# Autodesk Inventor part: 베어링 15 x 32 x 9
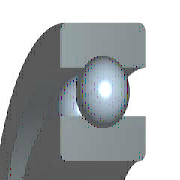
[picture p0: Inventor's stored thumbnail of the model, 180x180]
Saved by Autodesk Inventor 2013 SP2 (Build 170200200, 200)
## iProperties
IsCustomPart: 0
Created: 2012-02
Part Number: 베어링 15 x 32 x 9
Material: 강철, 연강
Description: 깊은 그루브 볼 베어링
Document SubType Name: Modeling
Standard: KS B 2023
Designer: mduedu
Standards Organization: KS
Language: ko-KR
Size Designation: 6002 - 15 x 32 x 9
Categories: <MemberInstance><Categories><Category DisplayName="샤프트 부품" InternalName="7f7aeb1f-a693-4053-b835-cee3144e0d98" Mnemonic="SHFT"><Category DisplayName="베어링" Inter
Density: 1 g/cm^3
Author: mduedu
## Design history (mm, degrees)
sketch "스케치" dims "d0" = 4.42 (= -0.26 x WD + 0.26 x BD)
  geometry: L1 (2.29, 11.75)-(6.71, 11.75); L2 (4.5, 11.75)-(4.5, 9.54); L3 (4.5, 11.75)-(4.5, 13.96); L4 (2.858, 10.271)-(0, 10.271); L5 (0, 7.5)-(9, 7.5); L6 (2.858, 13.229)-(0, 13.229); L7 (0, 16)-(9, 16); L8 (9, 7.5)-(9, 10.271); L9 (6.142, 10.271)-(9, 10.271); L10 (6.142, 13.229)-(9, 13.229); L11 (9, 16)-(9, 13.229); L12 (-1.4, 0)-(8.4, 0) reference; L13 (0, -0.3)-(0, 5.3) reference
  constraints: 22 end point, 4 point on line, 2 collinear, 2 perpendicular, 2 symmetric about line, 1 midpoint, 1 parallel, 14 other
  dimensions: "d9" = 15 diameter of L5 L12 (= WD); "d11" = 32 diameter of L7 L12 (= BD); "d12" = 9 distance between parallel lines of L8 L13 (= KB); "d13" = 20.542 diameter of L9 L12 (= 0.326 x BD + 0.674 x WD)
revolve "본체" stored, may be unused: angle "d6" = 90 deg
revolve "볼" stored, may be unused: angle "d7" = 90 deg
pattern_circular "IDS_ARRAYBALL[SIMPL:T]" dims angle "d3" = 360 deg
body "Solid1"
fillet "모깎기1" dims "d1" = 0.3 (= KRS)
other parameters: "WD" = 15 [user parameter; used in 5 equation terms], "BD" = 32 [user parameter; used in 5 equation terms], "KB" = 9 [user parameter; used in 1 equation term], "KRS" = 0.3 [user parameter; used in 1 equation term], "d4" = 0, "d5" = 0, "d8" = 0, "d14" = 0, "d15" = 0, "BBA" = 0 [user parameter], "BC0" = 2850000 [user parameter], "BC" = 5590000 [user parameter], "BR" = 16 (= 0.5 x BD) [user parameter], "WR" = 7.5 (= 0.5 x WD) [user parameter]
